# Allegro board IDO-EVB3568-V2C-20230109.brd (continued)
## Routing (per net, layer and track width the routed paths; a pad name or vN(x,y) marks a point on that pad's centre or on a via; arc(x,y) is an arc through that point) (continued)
FE1_1_DP0: length 2.8
  TOP w0.114: U8.31 106.76,44.7 106.87,44.81 106.87,45.11 106.68,45.3 106.54,45.3 106.18,45.66 106.18,45.92 R69.1
FE1_1_DP1: length 33.9
  TOP w0.114: R56.1 125.95,19.05 L8.1 125.95,19.49 125.67,19.77 125.67,19.88 v1(125.91,20.12) 125.91,20.61 R308.1 ; U8.24 112.29,42.45 112.42,42.32 115.78,42.32 117.98,40.12 117.98,31.65 118.82,30.81 118.82,29.84 v1(119.12,29.54)
  BOTTOM w0.114: v1(125.91,20.12) 125.67,20.35 125.67,20.61 125.67,20.62 125.67,22.06 124.16,23.57 123.01,23.57 118.82,27.76 118.82,29.24 v1(119.12,29.54)
FE1_1_DP2: length 45.7
  TOP w0.114: v1(114.08,11.76) 113.86,11.54 113.86,11.13 114.14,10.85 L9.1 114.14,10.41 R67.1 ; U8.21 112.11,40.95 112.26,40.81 112.69,40.81 113.11,41.22 115.01,41.22 117.25,38.99 117.25,29.62 116.41,28.78 114.38,28.78 113.51,27.91 113.51,25.26 113.1,24.85 112.77,24.85 v1(112.47,24.56)
  BOTTOM w0.114: v1(112.47,24.56) 112.19,24.84 110.02,24.84 109.3,24.12 109.3,14.94 111.65,12.58 113.56,12.58 113.86,12.27 113.86,11.99 v1(114.08,11.76)
FE1_1_DP3: length 41.5
  TOP w0.114: v1(103.44,11.76) 103.48,11.72 103.48,10.85 103.65,10.68 L10.1 103.85,10.39 R78.1 ; v1(111.65,25.81) 111.95,26.11 112.19,26.11 112.52,26.44 112.52,27.98 114.1,29.55 116,29.55 116.4,29.95 116.4,35.04 115.67,35.76 115.67,37.6 114.6,38.67 113.38,38.67 112.92,39.13 112.88,39.13 112.71,39.31 112.24,39.31 112.1,39.45 U8.18
  BOTTOM w0.114: v1(103.44,11.76) 103.19,12.01 103.19,12.52 107.76,17.08 107.76,24.19 109.67,26.11 111.35,26.11 v1(111.65,25.81)
FE1_1_DP4: length 22.8
  TOP w0.114: U8.15 110.52,37.95 110.39,37.82 108.6,37.82 106.91,39.51 106.91,42.41 v1(107.15,42.65) ; R341.2 101.97,49.67 101.97,49.43 102.45,48.96 103.96,48.96 104.1,48.82 104.1,48.69 v1(103.79,48.38)
  BOTTOM w0.114: v1(103.79,48.38) 104.09,48.68 104.09,48.87 104.37,49.15 106.92,49.15 107.51,48.56 107.51,47.09 106.87,46.46 106.87,42.94 v1(107.15,42.65)
FE1_1_XIN: length 7.1
  TOP w0.203: XT1.1 111.84,32.28 R68.1 111.51,32.21 111.07,32.21 110.64,32.65 C49.2 110.29,32.37 110.01,32.37 109.76,32.62 U8.12
FE1_1_XOUT: length 9.9
  TOP w0.203: U8.11 109.26,32.5 109.96,31.8 110.28,31.8 C51.2 110.76,31.51 110.95,31.7 111.26,31.7 R68.2 111.64,31.38 112.34,32.08 113.95,32.08 XT1.3
GMAC0_MCLKINOUT: length 55.7
  TOP w0.127: J2.230 26.92,54.23 27.38,54.69 v1(27.38,54.81) ; C131.2 v1(44.08,39.27) R219.2 R216.1
  BOTTOM w0.127: v1(44.08,39.27) 43.9,39.45 41.27,39.45 40.87,39.04 40.59,39.04 39.62,38.07 39.62,35.43 37.8,33.6 37.29,33.6 35.89,32.21 35.89,31.45 34.15,29.71 33.68,29.71 32.88,28.91 27.18,28.91 24.75,31.33 24.75,31.33 24.43,31.65 24.43,43.13 25.5,44.2 25.5,44.51 25.5,50.19 27.25,51.94 27.25,54.69 v1(27.38,54.81)
GMAC0_MDC: length 19.3
  TOP w0.127: U19.13 32,41.21 31.91,41.3 31.75,41.3 31.42,41.63 28.8,41.63 28.65,41.48 28.65,41.15 28.52,41.02 26.95,41.02 26.07,41.9 26.07,42.18 25.73,42.52 25.73,44.88 26.64,45.79 26.64,52.25 26.42,52.47 J2.232
GMAC0_MDIO: length 19.7
  TOP w0.127: U19.14 31.99,40.81 31.83,40.97 31.7,40.97 31.29,41.38 29.7,41.38 R249.1 29.06,40.74 26.82,40.74 25.78,41.78 25.78,42.06 25.45,42.39 25.45,44.96 26.39,45.9 26.39,51.99 25.92,52.46 J2.234
GMAC0_RSTN_GPIO2_D5: length 65.7
  TOP w0.127: J2.77 67.17,59.81 66.98,59.61 66.95,59.61 v1(66.9,59.56) ; R248.1 27,41.63 25.98,42.65 25.98,44.75 27.15,45.92 29.24,45.92 30.26,46.95 30.26,47.66 31.45,48.84 33.22,48.84 33.71,48.36 35.05,48.36 36.73,46.69 38.43,46.69 39.83,45.29 41.22,45.29 41.45,45.52 42.06,45.52 v1(42.19,45.39)
  BOTTOM w0.127: v1(66.9,59.56) 67.13,59.33 67.13,47.19 64.85,44.91 55.47,44.91 53.39,46.99 52.22,46.99 50.39,45.16 42.72,45.16 42.69,45.19 42.39,45.19 v1(42.19,45.39)
GMAC0_RXCLK: length 44
  TOP w0.127: C147.2 34.37,31.19 v1(34.11,31.45) R256.2 ; v1(28.52,55.83) 28.4,55.96 28.4,60.4 28.67,60.68 J2.223
  BOTTOM w0.127: v1(28.52,55.83) 28.27,55.58 28.27,53.9 28.08,53.71 28.08,51.98 26.29,50.19 26.29,45.49 27,44.78 27,41.61 25.3,39.9 25.3,31.55 27.3,29.54 32.33,29.54 34.11,31.32 v1(34.11,31.45)
GMAC0_RXD0: length 33.6
  TOP w0.127: v1(29.79,54.56) 29.41,54.56 28.92,54.07 J2.222 ; R252.2 v1(32.08,31.57)
  BOTTOM w0.127: v1(32.08,31.57) 31.32,30.81 27.58,30.81 26.37,32.03 26.37,38.76 28.02,40.41 28.02,45.42 27.41,46.02 27.41,49.66 29.13,51.38 29.13,53.14 29.79,53.8 v1(29.79,54.56)
GMAC0_RXD1: length 38.5
  TOP w0.127: R253.2 v1(31.06,31.57) ; J2.224 28.42,54.08 29.6,55.26 v1(29.81,55.26)
  BOTTOM w0.127: v1(31.06,31.57) 31.57,32.08 32.33,32.08 32.59,31.83 32.59,31.32 31.83,30.56 27.46,30.56 26.11,31.9 26.11,38.89 27.76,40.54 27.76,45.29 27.15,45.9 27.15,49.78 28.88,51.51 28.88,53.26 29.3,53.68 29.3,54.75 v1(29.81,55.26)
GMAC0_RXD2: length 36.9
  TOP w0.127: J2.219 29.67,57.6 30.94,56.34 v1(30.94,55.6) ; R254.2 v1(30.05,31.57)
  BOTTOM w0.127: v1(30.05,31.57) 29.54,31.06 27.71,31.06 26.62,32.16 26.62,38.63 28.27,40.28 28.27,45.54 27.66,46.15 27.66,49.53 29.39,51.26 29.39,53.01 30.43,54.05 30.43,55.07 30.94,55.58 v1(30.94,55.6)
GMAC0_RXD3: length 35.5
  TOP w0.127: v1(30.94,54.91) 30.43,55.42 30.43,56.34 29.41,57.35 29.41,60.4 29.17,60.64 J2.221 ; R255.2 v1(29.03,31.57)
  BOTTOM w0.127: v1(30.94,54.91) 30.94,54.18 29.64,52.88 29.64,51.13 27.91,49.4 27.91,46.28 28.57,45.62 28.57,40.21 26.87,38.51 26.87,32.28 27.84,31.32 28.78,31.32 v1(29.03,31.57)
GMAC0_RXDV_CRS: length 39.5
  TOP w0.127: R257.2 v1(33.1,31.57) ; J2.226 27.92,54.09 28.65,54.81 28.65,55.19 29.41,55.96 v1(29.92,55.96)
  BOTTOM w0.127: v1(33.1,31.57) 33.1,31.32 32.08,30.3 27.33,30.3 25.86,31.78 25.86,39.01 27.51,40.67 27.51,45.16 26.9,45.77 26.9,49.91 28.63,51.64 28.63,53.39 29.03,53.8 29.03,55.14 29.84,55.96 v1(29.92,55.96)
GMAC0_TXCLK: length 3
  TOP w0.127: J2.229 27.17,62.9 27.1,62.97 C134.2 R234.1
GMAC0_TXCLK_: length 42.4
  TOP w0.127: v1(25.35,65.23) C135.2 25.37,64.53 26.21,64.53 R234.2 ; v1(30.53,38.05) 31.83,38.05 32.19,38.41 U19.20
  BOTTOM w0.127: v1(30.53,38.05) 29.67,38.91 29.67,45.29 28.42,46.53 28.42,49.15 30.15,50.88 30.15,52.63 34.26,56.74 34.26,57.84 34.75,58.32 34.75,62.94 33.76,63.93 27.03,63.93 25.73,65.23 v1(25.35,65.23)
GMAC0_TXD0: length 2.6
  TOP w0.127: J2.216 30.42,51.21 R224.1
GMAC0_TXD0_: length 13.5
  TOP w0.127: v1(31.19,39.21) U19.18 ; R224.2 30.81,48.59 29.67,47.45 v1(29.67,47.24)
  BOTTOM w0.127: v1(29.67,47.24) 29.67,46.81 31.45,45.03 31.45,41.48 30.82,40.86 30.82,40.42 31.19,40.06 v1(31.19,39.21)
GMAC0_TXD1: length 2.5
  TOP w0.127: R227.1 29.92,50.95 J2.218
GMAC0_TXD1_: length 13.5
  TOP w0.127: v1(30.68,39.83) 30.81,39.95 31.14,39.95 31.49,39.61 U19.17 ; R227.2 29.9,49.82 v1(29.9,48.72)
  BOTTOM w0.127: v1(29.9,48.72) 29.9,48.16 29.18,47.45 29.18,46.91 31.19,44.91 31.19,41.61 30.56,40.97 30.56,39.95 v1(30.68,39.83)
GMAC0_TXD2: length 2.5
  TOP w0.127: J2.225 28.17,62.85 R228.1
GMAC0_TXD2_: length 36
  TOP w0.127: U19.16 31.8,40.01 31.72,40.08 v1(31.67,40.08) ; v1(28.19,65.2) 28.89,64.51 R228.2
  BOTTOM w0.127: v1(28.19,65.2) 28.7,64.69 34.19,64.69 35.51,63.37 35.51,57.91 35.03,57.43 35.03,56.36 30.94,52.27 30.94,48.66 30.43,48.15 30.43,46.81 31.95,45.29 31.95,40.36 v1(31.67,40.08)
GMAC0_TXD3: length 2.3
  TOP w0.127: R231.1 27.67,63.27 J2.227
GMAC0_TXD3_: length 36.2
  TOP w0.127: R231.2 27.69,64.84 27.69,64.97 v1(27.46,65.2) ; v1(31.32,40.67) 31.37,40.72 31.7,40.72 32.01,40.41 U19.15
  BOTTOM w0.127: v1(27.46,65.2) 28.22,64.44 34.01,64.44 35.26,63.19 35.26,58.06 34.77,57.58 34.77,56.47 30.68,52.38 30.68,48.77 30.18,48.26 30.18,46.69 31.7,45.16 31.7,41.05 v1(31.32,40.67)
GMAC0_TXEN: length 2.7
  TOP w0.127: J2.220 29.42,51.46 R232.1
GMAC0_TXEN_: length 14.4
  TOP w0.127: U19.19 31.82,38.81 v1(31.67,38.66) ; v1(29.24,48.16) 29.41,48.34 29.41,49.23 28.78,49.86 R232.2
  BOTTOM w0.127: v1(29.24,48.16) 28.93,47.85 28.93,46.79 30.56,45.16 30.56,43.64 30.18,43.26 30.18,39.45 30.96,38.66 v1(31.67,38.66)
GMAC1_MCLKINOUT_M1: length 22.7
  TOP w0.127: J2.54 72.92,54.05 72.42,54.56 v1(71.6,54.56) ; R271.2 v1(67.19,38.3) C155.2 R270.1
  BOTTOM w0.127: v1(71.6,54.56) 71.6,54.2 70.43,53.04 70.43,43.2 67.64,40.41 67.64,38.75 v1(67.19,38.3)
GMAC1_MDC_M1: length 39.7
  TOP w0.127: v1(56.46,41.45) 56.74,41.45 57.12,41.08 U20.13 ; J2.48 74.42,54.25 74.12,54.56 v1(73.1,54.56)
  BOTTOM w0.127: v1(73.1,54.56) 73.1,53.54 70.94,51.38 70.94,42.88 68.15,40.08 68.15,38.18 67.51,37.54 62.18,37.54 61.29,36.65 57.1,36.65 55.58,38.18 55.58,40.56 v1(56.46,41.45)
GMAC1_MDIO_M1: length 54.2
  TOP w0.127: U20.14 57.13,40.68 56.97,40.84 56.34,40.84 56.08,40.59 56.08,39.83 R297.1 55.57,38.93 54.81,38.18 54.33,38.18 53.92,37.77 53.92,37.03 v1(53.67,36.78) ; v1(75.87,51.16) 75.23,51.16 73.92,52.47 J2.50
  BOTTOM w0.127: v1(53.67,36.78) 54.13,36.32 54.13,35.53 53.04,34.44 53.04,32.72 53.8,31.95 56.21,31.95 57.73,30.43 64.47,30.43 65.43,31.39 67.1,31.39 67.47,31.76 67.47,31.93 68.55,33.02 68.55,34.7 69.44,35.59 70.38,35.59 71.58,36.78 71.58,37.69 73.74,39.85 73.74,48.97 75.87,51.1 v1(75.87,51.16)
GMAC1_RSTN_GPIO2_D7: length 34
  TOP w0.127: R296.1 54.67,41.29 v1(55.09,40.87) ; v1(68.38,60.15) 68.3,60.15 68.17,60.27 J2.73
  BOTTOM w0.127: v1(55.09,40.87) 56.21,41.99 61.42,41.99 62.74,40.67 64.97,40.67 65.28,40.97 65.28,41.55 66.62,42.9 66.62,44.12 68.15,45.64 68.15,59.13 68.27,59.26 68.27,60.05 v1(68.38,60.15)
GMAC1_RXCLK_M1: length 40.4
  TOP w0.127: v1(75.63,60.08) 75.17,60.54 J2.45 ; C171.2 59.11,33.3 v1(58.88,33.53) R304.2
  BOTTOM w0.127: v1(58.88,33.53) 59.46,34.11 60.91,34.11 62.05,35.26 62.05,35.89 62.69,36.53 68.02,36.53 69.67,38.18 69.67,38.48 71.96,40.77 71.96,50.11 73.36,51.51 73.36,52.27 74.37,53.29 74.37,58.83 v1(75.63,60.08)
GMAC1_RXD0_M1: length 42.3
  TOP w0.127: R300.2 v1(56.85,33.6) ; J2.34 77.92,54.56 v1(77.93,54.56)
  BOTTOM w0.127: v1(56.85,33.6) 56.85,32.97 58.14,31.67 62.15,31.67 63.2,32.72 67.51,32.72 68.05,33.25 68.05,35.02 69.12,36.09 70.13,36.09 70.94,36.91 70.94,37.82 73.23,40.11 73.23,49.23 75.13,51.13 75.13,52.15 76.28,53.29 76.28,54.58 76.76,55.07 77.42,55.07 v1(77.93,54.56)
GMAC1_RXD1_M1: length 41.8
  TOP w0.127: v1(77.17,54.56) 77.42,54.3 J2.36 ; R301.2 v1(55.83,33.6)
  BOTTOM w0.127: v1(77.17,54.56) 76.53,53.92 76.53,53.04 75.39,51.89 75.39,51 73.48,49.1 73.48,39.98 71.2,37.69 71.2,36.76 70.28,35.84 69.27,35.84 68.3,34.87 68.3,33.12 67.64,32.46 63.3,32.46 62.23,31.39 58.04,31.39 v1(55.83,33.6)
GMAC1_RXD2_M1: length 45.8
  TOP w0.127: v1(76.35,62.69) 76.3,62.69 76.17,62.56 J2.41 ; v1(54.84,33.6) 54.84,34.14 R302.2
  BOTTOM w0.127: v1(76.35,62.69) 76.35,61.85 73.86,59.36 73.86,53.54 71.45,51.13 71.45,42.62 68.66,39.83 68.66,37.92 67.77,37.03 62.43,37.03 61.54,36.14 61.54,35.51 60.88,34.85 56.08,34.85 v1(54.84,33.6)
GMAC1_RXD3_M1: length 45.8
  TOP w0.127: R303.2 53.8,33.88 54.08,33.6 v1(54.15,33.6) ; J2.43 v1(75.67,62.53)
  BOTTOM w0.127: v1(75.67,62.53) 75.67,61.55 73.61,59.49 73.61,53.67 71.2,51.26 71.2,42.75 68.4,39.95 68.4,38.05 67.64,37.29 62.31,37.29 61.29,36.27 61.29,35.64 60.76,35.1 55.65,35.1 v1(54.15,33.6)
GMAC1_RXDV_CRS_M1: length 37.7
  TOP w0.127: v1(75.39,54.56) 76.4,54.56 76.92,54.04 J2.38 ; R305.2 58.18,32.01 v1(58.43,32.26)
  BOTTOM w0.127: v1(58.43,32.26) 59.01,32.84 62.56,32.84 62.94,33.22 67.26,33.22 67.51,33.48 67.51,35.23 68.88,36.6 69.88,36.6 70.43,37.16 70.43,38.07 72.72,40.36 72.72,49.48 74.63,51.38 74.63,52.4 75.39,53.16 v1(75.39,54.56)
GMAC1_TXCLK_M1: length 3.6
  TOP w0.127: R282.1 C158.2 76.53,63.5 77.01,63.02 77.01,62.61 76.67,62.27 J2.39
GMAC1_TXCLK_M1_: length 44.9
  TOP w0.127: R282.2 77.47,64.73 C159.2 73.99,65.61 72.54,64.16 72.54,63.3 v1(72.31,63.07) ; v1(56.85,37.8) 57.33,38.28 U20.20
  BOTTOM w0.127: v1(56.85,37.8) 57.1,38.05 65.66,38.05 67.13,39.52 67.13,40.72 69.93,43.51 69.93,53.67 70.43,54.18 70.43,57.61 71.55,58.72 71.55,61.26 71.96,61.67 71.96,62.71 v1(72.31,63.07)
GMAC1_TXD0_M1: length 2.9
  TOP w0.127: J2.47 74.67,62.23 74.88,62.43 74.88,63.45 75.19,63.76 R272.1
GMAC1_TXD0_M1_: length 42.2
  TOP w0.127: v1(56.91,38.91) 57.07,39.08 U20.18 ; R272.2 75.39,64.66 v1(75,64.27)
  BOTTOM w0.127: v1(75,64.27) 74.43,64.27 73.91,63.75 73.51,63.75 73.05,64.21 71.83,64.21 71.45,63.83 71.45,61.93 71.03,61.5 71.03,58.98 69.16,57.11 69.16,45.15 67.67,43.65 67.67,42.39 66.34,41.07 66.34,39.9 65.33,38.89 64.54,38.89 63.88,39.55 63.3,39.55 63.07,39.32 57.86,39.32 57.45,38.91 v1(56.91,38.91)
GMAC1_TXD1_M1: length 2.6
  TOP w0.127: J2.49 74.17,62.24 74.63,62.69 74.63,63.46 R275.1
GMAC1_TXD1_M1_: length 41.3
  TOP w0.127: v1(56.49,39.46) 56.54,39.41 57.28,39.41 57.35,39.48 U20.17 ; v1(73.69,64.24) 74.11,64.66 R275.2
  BOTTOM w0.127: v1(73.69,64.24) 73.43,64.49 71.73,64.49 71.2,63.96 71.2,62.05 70.76,61.62 70.76,59.08 68.91,57.23 68.91,45.26 67.41,43.76 67.41,42.52 66.04,41.15 66.04,40.06 65.15,39.17 64.64,39.17 63.98,39.83 63.2,39.83 62.94,39.57 57.73,39.57 57.56,39.4 56.55,39.4 v1(56.49,39.46)
GMAC1_TXD2_M1: length 3.7
  TOP w0.127: J2.35 77.67,62.28 78.33,62.94 79.14,62.94 R276.1
GMAC1_TXD2_M1_: length 45.4
  TOP w0.127: v1(57.05,39.88) U20.16 ; R276.2 79.43,64.66 v1(79.38,64.72)
  BOTTOM w0.127: v1(57.05,39.88) 59.06,39.88 59.77,40.59 60.43,40.59 60.88,40.13 65.28,40.13 65.79,40.64 65.79,41.3 67.13,42.65 67.13,43.87 68.66,45.39 68.66,57.4 70.49,59.23 70.49,61.73 70.94,62.18 70.94,64.08 71.6,64.74 77.27,64.74 77.77,64.24 78.36,64.24 78.84,64.72 v1(79.38,64.72)
GMAC1_TXD3_M1: length 3
  TOP w0.127: R279.1 78.65,63.76 77.17,62.29 J2.37
GMAC1_TXD3_M1_: length 44.7
  TOP w0.127: v1(56.57,40.36) 57.25,40.36 57.33,40.28 U20.15 ; v1(78.16,64.72) 78.21,64.66 R279.2
  BOTTOM w0.127: v1(78.16,64.72) 77.88,65 71.48,65 70.69,64.21 70.69,62.31 70.23,61.85 70.23,59.36 68.4,57.53 68.4,45.52 66.88,43.99 66.88,42.77 65.53,41.43 65.53,40.77 65.18,40.41 61.01,40.41 60.58,40.84 59.64,40.84 59.16,40.36 v1(56.57,40.36)
GMAC1_TXEN_M1: length 3.2
  TOP w0.127: R280.1 78.42,50.83 J2.32
GMAC1_TXEN_M1_: length 52.7
  TOP w0.127: U20.19 57.35,38.68 57.1,38.43 56.72,38.43 56.34,38.81 55.83,38.81 54.94,37.92 54.46,37.92 54.18,37.64 54.18,36.58 v1(53.64,36.04) ; v1(78.33,49.73) 78.66,49.41 R280.2
  BOTTOM w0.127: v1(53.64,36.04) 53.64,35.46 52.78,34.59 52.78,31.7 53.54,30.94 56.85,30.94 57.61,30.18 66.24,30.18 67.72,31.66 67.72,31.83 68.81,32.91 68.81,34.59 69.55,35.33 70.51,35.33 71.83,36.65 71.83,37.54 73.99,39.7 73.99,48.82 74.78,49.61 78.21,49.61 v1(78.33,49.73)
HDMI_TX_CEC_PORT: length 7.7
  TOP w0.127: Q5.3 68.17,75.87 67.82,76.23 66.09,76.23 65.74,76.58 65.74,77.5 65.23,78 D44.1 65.23,78.82 64.75,79.29 J14.13
HDMI_TX_CLKN: length 25.5
  TOP w0.102: L19.2 64.15,74.44 63.89,74.17 63.89,74.06 v1(64.11,73.84) ; J2.147 47.67,62.23 47.55,62.36 47.55,63.04 v1(47.77,63.26)
  L3-POW w0.097: v1(47.77,63.26) 47.58,63.45 47.58,64.05 47.8,64.27 49.45,64.27 55.95,70.77 59.18,70.77 59.39,70.56 59.39,70.28 59.66,70.01 60.26,70.01 60.53,70.28 60.53,70.56 61.63,71.66 62.31,71.66 63.92,73.27 63.92,73.65 v1(64.11,73.84)
HDMI_TX_CLKN_: length 4.9
  TOP w0.102: L19.3 64.15,76.33 63.87,76.62 63.87,76.85 63.99,76.97 D41.5 D41.6 63.99,78.6 63.88,78.72 63.88,79.12 64.25,79.49 J14.12
HDMI_TX_CLKP: length 25.5
  TOP w0.102: v1(63.42,73.84) 63.64,74.06 63.64,74.16 63.35,74.44 L19.1 ; J2.149 47.17,62.24 47.3,62.36 47.3,63.04 v1(47.08,63.26)
  L3-POW w0.097: v1(63.42,73.84) 63.62,73.63 63.62,73.39 62.19,71.96 61.5,71.96 60.23,70.69 60.23,70.4 60.13,70.31 59.78,70.31 59.68,70.4 59.68,70.69 59.3,71.07 55.83,71.07 49.33,64.57 47.68,64.57 47.28,64.17 47.28,63.47 v1(47.08,63.26)
HDMI_TX_CLKP_: length 4.9
  TOP w0.102: J14.10 63.25,79.49 63.62,79.12 63.62,78.74 63.49,78.6 D41.7 D41.4 63.49,77 63.61,76.87 63.61,76.62 63.35,76.36 L19.4
HDMI_TX_D0N: length 25.6
  TOP w0.102: J2.155 45.67,62.21 45.8,62.33 45.8,62.56 46.09,62.86 46.09,63.89 45.99,63.99 45.89,63.99 v1(45.67,63.78) ; v1(62.59,73.81) 62.36,74.04 62.36,74.15 62.64,74.43 L18.2
  L3-POW w0.097: v1(45.67,63.78) 45.88,63.98 46.24,63.98 47.32,65.05 49.1,65.05 55.6,71.56 60.42,71.56 61.33,72.47 61.93,72.47 62.45,72.99 62.45,73.67 v1(62.59,73.81)
HDMI_TX_D0N_: length 4.9
  TOP w0.102: L18.3 62.64,76.35 62.37,76.62 62.37,76.85 62.49,76.97 D41.2 D41.9 62.49,78.62 62.37,78.75 62.37,79.11 62.75,79.49 J14.9
HDMI_TX_D0P: length 25.5
  TOP w0.102: L18.1 61.84,74.43 62.11,74.16 62.11,74.02 v1(61.9,73.81) ; J2.153 46.17,62.21 46.05,62.33 46.05,62.45 46.35,62.75 46.35,64 46.1,64.25 45.89,64.25 v1(45.67,64.47)
  L3-POW w0.097: v1(45.67,64.47) 45.86,64.28 46.12,64.28 47.19,65.35 48.97,65.35 55.47,71.86 60.3,71.86 61.21,72.77 61.8,72.77 62.15,73.12 62.15,73.56 v1(61.9,73.81)
HDMI_TX_D0P_: length 4.8
  TOP w0.102: J14.7 61.75,79.5 62.12,79.13 62.12,78.75 61.99,78.62 D41.10 D41.1 61.99,76.97 62.12,76.85 62.12,76.62 61.84,76.35 L18.4
HDMI_TX_D1N: length 25.7
  TOP w0.102: J2.159 44.67,62.2 44.8,62.32 44.8,62.6 44.91,62.71 44.91,63.72 44.8,63.83 44.63,63.83 v1(44.4,63.6) ; L17.2 61.14,74.43 60.87,74.15 60.87,74.03 v1(61.09,73.82)
  L3-POW w0.097: v1(61.09,73.82) 60.91,73.64 60.91,73.15 60.1,72.34 55.24,72.34 48.74,65.84 46.03,65.84 45.19,65 45.19,64.1 44.92,63.82 44.62,63.82 v1(44.4,63.6)
HDMI_TX_D1N_: length 4.9
  TOP w0.102: J14.6 61.25,79.49 60.88,79.12 60.88,78.55 60.99,78.44 D40.6 D40.5 60.99,76.97 60.87,76.85 60.87,76.62 61.14,76.35 L17.3
HDMI_TX_D1P: length 25.6
  TOP w0.102: J2.157 45.17,62.19 45.05,62.32 45.05,62.5 45.16,62.61 45.16,63.83 44.91,64.08 44.61,64.08 v1(44.4,64.29) ; L17.1 60.34,74.43 60.62,74.16 60.62,74.04 v1(60.39,73.82)
  L3-POW w0.097: v1(60.39,73.82) 60.61,73.6 60.61,73.28 59.98,72.64 55.12,72.64 48.62,66.14 45.91,66.14 44.89,65.12 44.89,64.22 44.79,64.12 44.57,64.12 v1(44.4,64.29)
HDMI_TX_D1P_: length 4.9
  TOP w0.102: L17.4 60.34,76.35 60.62,76.62 60.62,76.85 60.49,76.97 D40.4 D40.7 60.49,78.42 60.62,78.55 60.62,79.13 60.25,79.5 J14.4
HDMI_TX_D2N: length 25.6
  TOP w0.102: v1(43.13,63.6) 43.35,63.82 43.54,63.82 43.66,63.7 43.66,62.63 43.8,62.5 43.8,62.34 43.67,62.22 J2.163 ; v1(59.6,73.84) 59.37,74.07 59.37,74.13 59.65,74.4 L16.2
  L3-POW w0.097: v1(43.13,63.6) 43.34,63.8 43.61,63.8 43.94,64.13 43.94,65.53 45.03,66.62 48.38,66.62 54.89,73.13 59.12,73.13 59.4,73.4 59.4,73.64 v1(59.6,73.84)
HDMI_TX_D2N_: length 4.9
  TOP w0.102: L16.3 59.65,76.37 59.37,76.65 59.37,76.87 59.49,77 D40.2 D40.9 59.49,78.4 59.38,78.52 59.38,78.99 59.75,79.36 J14.3
HDMI_TX_D2P: length 25.5
  TOP w0.102: L16.1 58.85,74.4 59.12,74.13 59.12,74.06 v1(58.9,73.84) ; v1(43.13,64.29) 43.35,64.07 43.65,64.07 43.92,63.8 43.92,62.74 44.05,62.6 44.05,62.33 44.17,62.2 J2.161
  L3-POW w0.097: v1(43.13,64.29) 43.32,64.1 43.49,64.1 43.64,64.25 43.64,65.65 44.91,66.92 48.25,66.92 54.76,73.43 59,73.43 59.1,73.53 59.1,73.65 v1(58.9,73.84)
HDMI_TX_D2P_: length 4.9
  TOP w0.102: L16.4 58.85,76.37 59.12,76.64 59.12,76.87 58.99,77 D40.1 D40.10 58.99,78.4 59.12,78.53 59.12,78.98 58.75,79.35 J14.1
HDMI_TX_HPD_PORT: length 6.2
  TOP w0.127: R107.2 69.93,77.05 R108.2 69.37,77.07 69.32,77.02 D46.1 68.48,77.37 68.48,77.42 68.2,77.7 68.2,78.28 67.75,78.73 J14.19
HDMI_TX_HPDIN: length 36.5
  TOP w0.127: R107.1 71.08,78.13 v1(71.45,78.13) ; J2.143 50.67,65.19 54.05,68.57 54.05,74.02 53.78,74.29 v1(53.78,74.3)
  BOTTOM w0.127: v1(71.45,78.13) 71.15,78.44 69.42,78.44 68.4,79.45 57.79,79.45 57.44,79.11 56.85,78.51 55.95,78.51 53.95,76.52 53.95,74.84 53.78,74.68 v1(53.78,74.3)
HDMI_TXDDC_SCL_PORT: length 12.3
  TOP w0.127: J14.15 65.75,78.75 D45.1 65.99,77.49 65.99,76.68 66.19,76.48 68.01,76.48 68.73,75.77 69.74,75.77 Q3.3 70.03,75.33 69.16,74.46 69.16,72.83 R104.1
HDMI_TXDDC_SDA_PORT: length 12.6
  TOP w0.127: J14.16 66.25,79.37 D47.1 67.61,77.93 68.22,77.32 68.22,76.63 68.75,76.1 71.45,76.1 71.89,75.66 71.89,75.48 Q4.3 71.69,75.48 70.89,74.68 70.89,73 71.17,72.72 R106.2
HDMITX_CEC_M0: length 28.1
  TOP w0.127: v2(74.98,71.03) 74.98,70.82 75.03,70.76 75.03,68.53 74.88,68.38 70.94,64.44 67.68,64.44 66.99,63.75 65.61,63.75 64.17,62.32 J2.89 ; Q5.2 68.55,73.88 68,73.33 R109.1 68.53,72.18 68.53,70.51 v1(68.55,70.48)
  BOTTOM w0.127: v2(74.98,71.03) 74.82,71.03 74.69,71.16 74.46,71.16 74.19,71.42 72.39,71.42 71.6,70.64 71.04,70.64 70.66,71.02 69.75,71.02 69.19,70.46 68.63,70.46 68.61,70.48 v1(68.55,70.48)
HOST_WAKE_BT: length 2.7
  TOP w0.127: U18.6 112.85,18.62 113.87,17.6 R394.2
HOST_WAKE_BT_H_GPIO1_D3: length 74.2
  TOP w0.127: v1(94.03,27) 93.6,27 93.47,26.87 93.47,26.03 91.72,24.28 89.28,24.28 87.53,26.04 82.7,26.04 82.37,26.37 82.37,35.76 82.25,35.89 82.25,40.72 81.42,41.54 J2.20 ; v1(116.15,17.6) R394.1
  BOTTOM w0.127: v1(94.03,27) 93.78,27.25 93.78,28.24 94.51,28.98 108.84,28.98 109.34,28.48 111.24,28.48 114.5,25.22 114.5,19.25 v1(116.15,17.6)
HP_SNS: length 231.3
  TOP w0.203: v1(122.61,74.07) 122.25,74.42 122.25,75.51 121.93,75.84 R81.1 120.22,77.23 120.22,81.74 121.67,83.19 121.67,85.88 121.11,86.44 115.65,86.44 J10.1 ; v1(36.78,27.25) 36.78,27.51 35.64,28.65 28.52,28.65 27.13,30.05 27.13,31.45 26.75,31.83 26.41,31.83 25.35,31.83 23.55,33.63 19.52,33.63 18.13,35.02 18.13,37.11 16.69,38.56 16.69,49.52 16.88,49.72 17.28,50.11 17.82,50.11 21.87,50.11 23.42,51.67 J2.244
  BOTTOM w0.203: v1(122.61,74.07) 123.19,74.07 125.27,71.98 125.27,68.76 124.79,68.28 124.79,64.95 125.27,64.47 125.27,61.7 127.73,59.24 127.73,48.99 126.97,48.23 126.97,40.61 125.93,39.57 114.55,39.57 112.52,37.54 112.09,37.54 109.55,35 101.17,35 100.57,34.4 96.92,34.4 94.65,32.13 89.28,32.13 88.47,31.32 87.58,31.32 86.46,30.2 86.46,29.31 84.99,27.84 84.99,26.95 75.39,17.35 75.39,13.16 69.75,7.52 39.47,7.52 38.3,8.69 37.85,8.69 36.65,9.88 36.65,12.88 36.98,13.21 36.98,26.29 36.78,26.49 v1(36.78,27.25)
HPL_OUT: length 217.1
  TOP w0.203: C72.2 115.11,74.94 R84.1 v1(115.77,74.22) ; J2.242 23.92,51.61 22.1,49.78 17.69,49.78 17.41,49.78 17.02,49.39 17.02,42.96 17.02,42.96 17.02,38.84 18.61,37.25 18.61,35.01 19.63,33.99 23.67,33.99 25.49,32.17 26.99,32.17 27.46,31.7 27.46,30.2 28.63,29.03 35.76,29.03 37.29,27.51 v1(37.29,26.75)
  BOTTOM w0.203: v1(37.29,26.75) 37.34,26.7 37.34,13.08 36.98,12.73 36.98,10.06 38.02,9.02 38.46,9.02 39.6,7.87 69.6,7.87 75.01,13.28 75.01,17.48 84.66,27.13 84.66,28.02 86.13,29.49 86.13,30.38 87.4,31.65 88.29,31.65 89.1,32.46 94.51,32.46 96.8,34.75 100.43,34.75 101.04,35.36 109.4,35.36 111.96,37.92 112.42,37.92 114.45,39.95 125.81,39.95 126.64,40.79 126.64,48.42 127.37,49.15 127.37,59.09 124.94,61.52 124.94,64.21 124.41,64.74 124.41,68.38 124.94,68.91 124.94,71.76 123.53,73.18 119.51,73.18 118.95,73.74 116.26,73.74 v1(115.77,74.22)
HPR_OUT: length 216.3
  TOP w0.203: C75.2 R82.1 v1(119.58,74.37) ; v1(36.27,26.77) 36.27,27.38 35.38,28.27 28.42,28.27 26.8,29.9 26.8,31.24 26.54,31.5 25.19,31.5 23.42,33.27 19.41,33.27 17.64,35.04 17.64,37.09 16.31,38.43 16.31,49.61 16.36,49.66 17.14,50.44 17.96,50.44 21.64,50.44 22.92,51.73 J2.246
  BOTTOM w0.203: v1(36.27,26.77) 36.27,26.52 36.63,26.16 36.63,13.34 36.32,13.03 36.32,9.73 37.72,8.33 38.18,8.33 39.32,7.19 69.93,7.19 75.77,13.03 75.77,17.22 85.32,26.77 85.32,27.66 86.79,29.13 86.79,30.02 87.71,30.94 88.6,30.94 89.46,31.8 94.84,31.8 97,33.96 100.63,33.96 101.3,34.62 109.68,34.62 112.22,37.16 112.62,37.16 114.66,39.19 126.06,39.19 127.33,40.46 127.33,48.08 128.07,48.82 128.07,59.41 125.6,61.87 125.6,64.67 125.2,65.07 125.2,68.05 125.6,68.45 125.6,72.16 123.19,74.57 122.33,74.57 121.62,73.86 120.09,73.86 v1(119.58,74.37)
HUB_RST: length 5.2
  TOP w0.254: U8.34 105.26,44.88 104.47,45.67 103.96,45.67 103.71,45.92 R53.2
  TOP w0.381: C48.2 R66.1 R53.2
HUB_RST_GPIO1_A4_D: length 25.2
  TOP w0.127: R53.1 102.69,48.16 99.72,48.16 98.07,46.51 v1(97.71,46.51) ; v1(84.02,51.54) 84.02,51.89 84.42,52.29 J2.8
  BOTTOM w0.127: v1(97.71,46.51) 97.41,46.81 95.61,46.81 94.72,47.7 89.87,47.7 85.55,52.02 84.51,52.02 v1(84.02,51.54)
I2C1_SCL: length 122.1
  TOP w0.127: v1(50.37,41.12) 50.75,41.5 50.75,42.85 50.27,43.33 50.27,46.71 47.7,49.28 47.7,52.05 47.92,52.27 J2.146 ; R311.2 127.14,29.08 125.26,30.96 125.16,30.96 124.93,31.19 124.66,31.19 124.16,31.7 120.85,31.7 119.76,32.79 119.76,35.56 120.6,36.4 120.6,41.61 v1(120.85,41.86)
  BOTTOM w0.127: v1(120.85,41.86) 120.35,41.35 117.68,41.35 117.17,41.86 113.74,41.86 109.42,37.54 106.5,37.54 105.74,36.78 100.28,36.78 99.9,36.4 97.22,36.4 94.42,39.19 78.05,39.19 67.26,28.4 56.72,28.4 55.96,29.16 52.65,29.16 51,30.81 51,39.04 50.37,39.68 50.37,40.46 50.37,40.46 v1(50.37,41.12)
I2C1_SCL_: length 6.3
  TOP w0.127: R311.7 128.91,29.08 130.51,30.68 132.28,30.68 J24.22
I2C1_SDA: length 122.5
  TOP w0.127: v1(121.36,41.35) 120.85,40.84 120.85,40.42 120.85,36.27 120.02,35.43 120.02,32.92 120.98,31.95 124.28,31.95 124.79,31.45 125.04,31.45 125.27,31.21 125.36,31.21 126.95,29.63 R311.1 ; v1(49.82,40.59) 49.82,41.28 50.5,41.96 50.5,42.72 50.01,43.21 50.01,46.58 47.45,49.15 47.45,53.23 J2.148
  BOTTOM w0.127: v1(121.36,41.35) 121.11,41.1 117.55,41.1 117.04,41.61 113.87,41.61 109.55,37.29 106.63,37.29 105.87,36.53 100.41,36.53 100.03,36.14 97.11,36.14 94.32,38.94 78.18,38.94 67.39,28.14 52.66,28.14 50.75,30.05 50.75,38.94 50.09,39.6 50.09,40.31 49.82,40.58 v1(49.82,40.59)
I2C1_SDA_: length 3.5
  TOP w0.127: R311.8 128.49,29.63 128.84,29.98 129.04,29.98 J24.21
I2C2_SCL_M0: length 65
  TOP w0.127: J2.150 46.92,52.16 47.19,51.89 47.19,49.02 49.76,46.46 49.76,42.79 v1(50.02,42.53) ; v1(39.28,20.39) 39.31,20.42 41.63,20.42 42.75,19.3 43.36,19.3 v1(43.74,18.92)
  BOTTOM w0.127: v1(39.28,20.39) 38.62,20.39 38.25,20.76 38.25,26.23 38.51,26.49 38.51,27.66 38.11,28.06 37.9,28.06 34.37,28.06 32.9,26.59 32.48,26.59 32.31,26.59 32.21,26.49 32.21,25.79 R111.1 R115.1 ; v1(43.74,18.92) 45.31,18.92 46.08,19.68 46.08,20.19 47.22,21.34 49.28,21.34 50.5,22.56 50.5,26.62 49.48,27.64 49.48,36.78 48.84,37.41 48.84,41.71 49.56,42.42 49.85,42.42 49.96,42.53 v1(50.02,42.53)
I2C2_SDA_M0: length 64.1
  TOP w0.127: v1(42.85,18.8) 41.48,20.17 39.77,20.17 39.47,19.86 39.19,19.86 39.08,19.97 38.39,19.97 38.19,20.18 v1(38.18,20.18) ; v1(49.76,41.91) 49.5,42.16 49.5,46.33 46.94,48.9 46.94,51.77 46.42,52.28 J2.152
  BOTTOM w0.127: v1(49.76,41.91) 49.74,41.88 49.71,41.88 49.1,41.27 49.1,37.54 49.73,36.91 49.73,27.76 50.75,26.75 50.75,22.43 49.4,21.08 47.35,21.08 46.33,20.07 46.33,19.56 45.21,18.44 43.26,18.44 42.9,18.8 v1(42.85,18.8) ; R116.1 33.81,25.13 R112.1 33.83,25.2 34.32,25.68 34.32,27.58 34.54,27.8 38.01,27.8 38.26,27.55 38.26,26.59 38,26.33 38,20.36 v1(38.18,20.18)
I2C3_SCL_M1: length 57.5
  TOP w0.127: J2.74 67.92,51.76 68.28,51.41 69.14,51.41 75.9,44.65 75.9,43.26 79.71,39.45 79.71,34.62 79.83,34.49 79.83,29.16 78.05,27.38 78.05,22.94 78.56,22.43 78.56,21.53 82.07,18.02 89.78,18.02 90.25,17.55 90.25,16.38 v1(90.12,16.26) ; R96.1 92.02,15.37 R92.1 92.68,15.5 v1(92.73,15.45)
  BOTTOM w0.127: v1(92.73,15.45) 92.35,15.82 90.55,15.82 v1(90.12,16.26)
I2C3_SDA_M1: length 54.5
  TOP w0.127: R97.1 R93.1 90.59,16.04 90.59,17.56 89.88,18.27 82.18,18.27 78.82,21.63 78.82,22.56 78.31,23.06 78.31,27.25 80.09,29.03 80.09,34.62 79.96,34.75 79.96,39.57 76.15,43.38 76.15,44.78 69.27,51.66 68.88,51.66 68.42,52.13 J2.72
I2C4_SCL_M0: length 53.3
  TOP w0.127: v1(81.25,25.98) 81.25,26.52 81.86,27.13 81.86,35.51 81.74,35.64 81.74,40.46 77.93,44.27 77.93,45.67 77.6,46 77.6,50.67 77.8,50.88 77.8,51.64 77.66,51.78 76.74,51.78 76.35,52.17 76.07,52.17 75.92,52.32 J2.42 ; R152.1 63.96,15.57 v1(64.21,15.82) 64.24,15.85 R155.1
  BOTTOM w0.127: v1(64.21,15.82) 65.61,17.22 71.45,17.22 79.83,25.6 80.87,25.6 v1(81.25,25.98)
I2C4_SDA_M0: length 54.4
  TOP w0.127: R154.1 62.94,16.31 v1(62.94,15.82) R153.1 ; v1(81.86,26.47) 81.86,26.75 82.12,27 82.12,35.64 81.99,35.76 81.99,40.59 78.18,44.4 78.18,45.8 77.85,46.13 77.85,50.55 78.05,50.75 78.05,51.77 77.74,52.08 76.83,52.08 76.42,52.48 J2.40
  BOTTOM w0.127: v1(62.94,15.82) 63.35,16.23 63.98,16.23 65.23,17.48 71.32,17.48 79.71,25.86 80.47,25.86 81.08,26.47 v1(81.86,26.47)
I2C5_SCL-HDMI: length 24.2
  TOP w0.127: Q3.2 70.53,73.06 R103.2 70.66,72.23 70.66,71.06 70.98,70.75 71.66,70.75 71.83,70.92 72.97,70.92 73.2,71.15 73.8,71.15 74.52,70.43 74.52,68.97 74.45,68.91 74.45,68.66 70.73,64.95 67.46,64.95 66.78,64.26 65.13,64.26 63.17,62.31 J2.93
I2C5_SCL_M0: length 68.6
  TOP w0.127: R327.1 75.08,39.57 74.63,39.57 74.22,39.17 v1(74.22,30.05) ; R327.1 75.34,39.88 74.4,40.82 74.4,42.37 75.39,43.36 75.39,44.4 68.91,50.88 67.64,50.88 66.92,51.59 J2.78 ; R327.1 75.39,39.78 R328.2 ; v1(47.21,17.11) 47.21,17.48 46.37,18.32 44.9,18.32 Q17.3
  BOTTOM w0.127: v1(47.21,17.11) 47.24,17.14 47.24,17.5 47.62,17.88 48.54,17.88 48.64,17.98 49.63,17.98 49.96,18.31 49.96,20.13 50.26,20.43 54.17,24.33 54.38,24.33 54.59,24.33 54.59,24.33 68.37,24.33 68.37,24.33 69,24.33 69.06,24.33 74.22,29.49 v1(74.22,30.05)
I2C5_SDA-HDMI: length 21.8
  TOP w0.127: Q4.2 72.44,73.82 72.44,72.76 R105.2 74.3,72.71 74.55,72.45 74.55,70.76 74.78,70.54 74.78,68.63 70.84,64.69 67.57,64.69 66.89,64.01 65.43,64.01 63.67,62.25 J2.91
I2C5_SDA_M0: length 74
  TOP w0.127: R326.1 77.06,41.71 79.45,39.32 79.45,34.11 v1(79.32,33.99) ; R326.1 76.43,41.71 76.43,42.34 75.64,43.13 75.64,44.53 69.01,51.16 67.87,51.16 67.42,51.6 J2.76 ; R326.1 76.33,41.62 R329.2 ; Q16.3 41.87,17.35 42.62,17.35 42.81,17.53 43.19,17.53 44.28,18.63 46.42,18.63 47.64,17.41 v1(47.92,17.41)
  BOTTOM w0.127: v1(79.32,33.99) 79.3,33.96 77.77,33.96 76.53,32.72 76.53,31.39 69.22,24.08 69.11,24.08 54.48,24.08 54.48,24.08 54.27,24.08 50.22,20.02 50.22,18.21 49.74,17.73 48.79,17.73 48.31,17.25 48.08,17.25 v1(47.92,17.41)
I2C_SCL_RTC: length 2.3
  TOP w0.127: R328.1 77.93,39.78 78.07,39.63 U21.6
I2C_SDA_RTC: length 3.3
  TOP w0.127: R329.1 77.6,40.72 78.72,39.59 U21.5
LAN0_A+: length 54.8
  TOP w0.102: v1(35.36,47.4) 35.14,47.18 35.14,47.1 35.43,46.81 36.02,46.81 36.66,46.18 38.01,46.18 38.27,45.93 38.27,45.7 R223.2 ; D84.4 v1(30.39,68.15) 30.39,68 30.49,67.89 31.57,67.89 31.7,68.02 31.7,68.94 D57.A 31.95,68.94 31.95,68.02 32.08,67.89 32.23,67.89 32.33,68 32.33,72.36 28.67,76.02 27.89,76.02 27.13,75.26 27.13,74.18 27.57,73.74 28.52,73.74 28.78,73.99 28.78,74.37 28.27,74.88
  BOTTOM w0.102: v1(35.36,47.4) 35.15,47.6 35.15,51.43 38.06,54.34 38.06,56.09 38.56,56.59 38.56,65.99 36.4,68.15 32.08,68.15 31.83,67.89 30.64,67.89 v1(30.39,68.15)
LAN0_A-: length 54.6
  TOP w0.102: R222.2 38.01,45.7 38.01,45.82 37.91,45.92 36.55,45.92 35.92,46.56 35.33,46.56 34.89,47 34.89,47.16 v1(34.65,47.4) ; D84.3 v1(30.39,67.39) 30.39,67.54 30.49,67.64 31.57,67.64 31.7,67.51 31.7,66.59 D57.C 31.95,66.59 31.95,67.26 32.59,67.89 32.59,72.47 28.78,76.28 27.78,76.28 26.87,75.37 26.87,74.07 27.32,73.62 27.32,72.66 J22.3
  BOTTOM w0.102: v1(30.39,67.39) 30.64,67.64 31.93,67.64 32.19,67.89 36.29,67.89 38.3,65.88 38.3,56.69 37.81,56.2 37.81,54.44 34.9,51.54 34.9,47.64 v1(34.65,47.4)
LAN0_B+: length 54.8
  TOP w0.102: v1(33.86,47.27) 33.63,47.04 33.63,46.89 34.47,46.05 35.13,46.05 35.38,45.8 35.38,45.64 35.67,45.36 R221.2 ; v1(28.69,73.18) 28.47,72.96 28.47,71.86 29.16,71.17 29.16,70.58 28.76,70.18 28.29,70.18 27.66,70.82 26.75,70.82 26.37,70.43 26.37,68.02 26.49,67.89 26.62,67.89 26.87,68.15 26.87,68.94 D56.A 27.13,68.94 27.13,68.02 27.25,67.89 28.39,67.89 28.49,68 v1(28.49,68.15) D84.6
  BOTTOM w0.102: v1(33.86,47.27) 33.63,47.5 33.63,51.05 37.31,54.73 37.31,56.41 37.8,56.89 37.8,64.97 35.84,66.93 30,66.93 29.03,67.89 28.74,67.89 v1(28.49,68.15) ; v1(28.69,73.18) 28.47,73.4 28.47,73.63 28.2,73.91 24.42,73.91 24.21,74.12 24.21,74.63 24.46,74.88 25.73,74.88
LAN0_B-: length 54.7
  TOP w0.102: v1(33.16,47.27) 33.38,47.05 33.38,46.78 34.36,45.8 35.03,45.8 35.13,45.69 35.13,45.61 R220.2 ; v1(28,73.18) 28.22,72.96 28.22,71.75 28.91,71.07 28.91,70.69 28.65,70.43 28.4,70.43 27.76,71.07 26.64,71.07 26.11,70.54 26.11,67.92 26.39,67.64 26.62,67.64 26.87,67.39 26.87,66.59 D56.C 27.13,66.59 27.13,67.39 27.38,67.64 28.39,67.64 28.49,67.54 v1(28.49,67.39) D84.1
  BOTTOM w0.102: v1(28.49,67.39) 28.74,67.64 28.93,67.64 29.89,66.67 35.73,66.67 37.54,64.87 37.54,57 37.06,56.52 37.06,54.84 36.46,54.24 33.38,51.16 33.38,47.49 v1(33.16,47.27) ; J22.7 23.23,73.65 28.1,73.65 28.22,73.53 28.22,73.4 v1(28,73.18)
LAN0_C+: length 54.6
  TOP w0.102: v1(32.87,46.65) 32.66,46.44 32.66,46.28 32.77,46.18 33.27,46.18 33.63,45.82 33.63,45.71 R425.2 ; v1(23,68.28) D83.4 23.36,69.24 23.57,69.04 23.57,68.15 23.7,68.02 24.08,68.02 24.21,68.15 24.21,68.86 D55.A 24.59,68.89 24.59,68.15 24.71,68.02 24.86,68.02 25.22,68.38 25.22,69.8 24.97,70.05 24.2,70.05 23.95,70.3 23.95,70.95 24.2,71.2 25.1,71.2 25.48,71.58 25.48,73.12 24.57,74.03 24,74.03 23.83,73.86 23.83,72.97 24.46,72.34
  BOTTOM w0.102: v1(32.87,46.65) 32.64,46.88 32.64,47.9 32.46,48.08 32.46,51.02 36.53,55.09 36.53,56.71 37.03,57.22 37.03,64.59 35.43,66.19 29.67,66.19 28.93,66.93 28.22,66.93 27.13,68.02 23.25,68.02 v1(23,68.28)
LAN0_C-: length 54.6
  TOP w0.102: 23.19,74.88 23.78,74.29 24.67,74.29 25.73,73.23 25.73,71.47 25.2,70.94 24.31,70.94 24.21,70.84 24.21,70.41 24.31,70.31 25.07,70.31 25.48,69.9 25.48,68.28 24.97,67.77 24.71,67.77 24.59,67.64 24.59,66.65 D55.C 24.21,66.67 24.21,67.64 24.08,67.77 23.7,67.77 23.57,67.64 23.57,66.62 23.49,66.54 D83.3 v1(23,67.51) ; R424.2 33.38,45.64 33.38,45.72 33.17,45.92 32.66,45.92 32.41,46.17 32.41,46.43 v1(32.18,46.66)
  BOTTOM w0.102: v1(23,67.51) 23.25,67.77 27.02,67.77 28.11,66.67 28.83,66.67 29.56,65.94 35.33,65.94 36.78,64.49 36.78,57.33 36.27,56.82 36.27,55.19 32.21,51.13 32.21,47.98 32.38,47.8 32.38,46.86 v1(32.18,46.66)
LAN0_D+: length 54.9
  TOP w0.102: 20.65,74.88 20.29,74.52 20.29,73.54 20.78,73.05 20.78,71.45 21.03,71.2 21.92,71.2 22.17,70.95 22.17,70.3 21.92,70.05 19.38,70.05 19.18,69.85 19.18,68.15 19.31,68.02 19.38,68.02 19.51,68.15 19.51,68.89 D54.A 19.89,68.86 19.89,68.15 20.02,68.02 20.65,68.02 20.9,68.28 20.9,69.05 D83.6 21.29,69.06 21.29,68.57 21.61,68.25 v1(21.73,68.25) ; R215.2 30.97,45.71 30.97,45.85 31.7,46.58 31.7,47.35 v1(31.92,47.57)
  BOTTOM w0.102: v1(21.73,68.25) 21.99,68 22.25,68 22.5,67.74 22.5,67.12 22.82,66.8 26.95,66.8 27.56,66.19 28.6,66.19 29.34,65.46 35.03,65.46 36.27,64.21 36.27,57.53 35.79,57.04 35.79,55.45 31.7,51.36 31.7,47.78 v1(31.92,47.57)
LAN0_D-: length 54.8
  TOP w0.102: J22.9 19.38,72.52 20.07,73.21 20.26,73.21 20.52,72.95 20.52,71.34 20.93,70.94 21.82,70.94 21.92,70.84 21.92,70.41 21.82,70.31 19.27,70.31 18.92,69.96 18.92,68.05 19.2,67.77 19.38,67.77 19.51,67.64 19.51,66.65 D54.C 19.89,66.67 19.89,67.64 20.02,67.77 20.65,67.77 20.9,67.51 20.9,66.74 D83.1 21.29,66.73 21.29,67.17 21.61,67.49 v1(21.73,67.49) ; R214.2 30.72,45.77 30.72,45.96 31.45,46.69 31.45,47.35 v1(31.23,47.57)
  BOTTOM w0.102: v1(31.23,47.57) 31.45,47.78 31.45,51.46 35.53,55.55 35.53,57.15 36.02,57.63 36.02,64.11 34.92,65.2 29.23,65.2 28.5,65.94 27.45,65.94 26.84,66.55 22.71,66.55 22.25,67.01 22.25,67.64 22.15,67.74 21.99,67.74 v1(21.73,67.49)
LAN1_A+: length 72.2
  TOP w0.102: 47.07,74.88 47.57,74.88 48.08,74.37 48.08,73.84 47.85,73.61 46.24,73.61 45.92,73.92 45.92,75.28 46.54,75.9 47.6,75.9 49.73,73.76 49.73,68 49.63,67.89 49.48,67.89 49.41,67.97 49.41,68.91 D61.A 49.1,68.91 49.1,68.02 48.97,67.89 48.02,67.89 v1(47.76,68.15) D82.4 ; R266.2 63.79,45.7 63.79,46.7 62.28,48.21 62.28,49.25 61.55,49.99 61.07,49.99 60.81,50.24 60.81,50.35 v1(61,50.55)
  BOTTOM w0.102: v1(47.76,68.15) 48.02,67.89 48.21,67.89 48.34,68.02 48.34,69.06 47.82,69.57 43.79,69.57 42.37,68.15 42.37,66.65 41.86,66.14 41.86,58.37 42.57,57.66 51.63,57.66 52.12,58.14 57.81,58.14 59.89,56.06 59.89,53.92 60.78,53.04 60.78,50.77 v1(61,50.55)
LAN1_A-: length 72.3
  TOP w0.102: D82.3 v1(47.76,67.39) 48.02,67.64 48.97,67.64 49.1,67.51 49.1,66.62 D61.C 49.4,66.61 49.4,67.56 49.48,67.64 49.74,67.64 49.99,67.89 49.99,73.86 47.7,76.15 46.43,76.15 45.67,75.39 45.67,73.82 45.92,73.56 45.92,72.47 J23.3 ; v1(60.31,50.55) 60.55,50.3 60.55,50.14 60.96,49.73 61.44,49.73 62.03,49.15 62.03,48.11 63.54,46.6 63.54,45.7 R265.2
  BOTTOM w0.102: v1(47.76,67.39) 48.02,67.64 48.31,67.64 48.59,67.92 48.59,69.16 47.93,69.82 43.68,69.82 42.11,68.25 42.11,66.75 41.61,66.24 41.61,58.26 42.47,57.4 51.74,57.4 52.22,57.89 57.71,57.89 59.64,55.96 59.64,53.82 60.53,52.93 60.53,50.77 v1(60.31,50.55)
LAN1_B+: length 72.5
  TOP w0.102: D82.6 v1(45.86,68.15) 45.61,67.89 44.65,67.89 44.53,68.02 44.53,68.94 D60.A 44.27,68.94 44.27,68.02 44.15,67.89 44,67.89 43.89,68 43.89,69.82 44.12,70.05 48.95,70.05 49.23,70.33 49.23,70.92 48.95,71.2 47.3,71.2 47.19,71.3 47.19,72.88 v1(47.41,73.1) ; R264.2 61.04,45.73 61.04,48.2 60.67,48.58 60.67,48.73 v1(60.89,48.95)
  BOTTOM w0.102: v1(45.86,68.15) 46.12,67.89 46.25,67.89 46.38,68.02 46.38,68.6 46.15,68.83 44.2,68.83 43.26,67.89 43.26,66.39 42.6,65.73 42.6,58.75 42.96,58.39 51.3,58.39 51.79,58.88 58.24,58.88 60.66,56.46 60.66,54.28 61.85,53.09 61.85,50.04 61.42,49.61 61.04,49.61 60.67,49.23 60.67,49.16 v1(60.89,48.95) ; v1(47.41,73.1) 47.19,73.32 47.19,73.56 46.96,73.79 43.21,73.79 43,73.99 43,75.64 43.13,75.77 44.15,75.77 44.53,75.39 44.53,74.88
LAN1_B-: length 72.5
  TOP w0.102: v1(60.19,48.95) 60.41,48.73 60.41,48.47 60.79,48.1 60.79,45.74 R263.2 ; D82.1 v1(45.86,67.39) 45.61,67.64 44.65,67.64 44.53,67.51 44.53,66.59 D60.C 44.27,66.59 44.27,67.51 44.15,67.64 43.89,67.64 43.64,67.89 43.64,69.93 44.02,70.31 48.84,70.31 48.97,70.43 48.97,70.82 48.84,70.94 47.19,70.94 46.94,71.2 46.94,72.88 v1(46.72,73.1)
  BOTTOM w0.102: J23.7 41.91,73.53 46.86,73.53 46.94,73.45 46.94,73.32 v1(46.72,73.1) ; v1(60.19,48.95) 60.41,49.17 60.41,49.34 60.93,49.86 61.31,49.86 61.59,50.14 61.59,52.98 60.4,54.18 60.4,56.36 58.14,58.62 51.89,58.62 51.41,58.14 42.85,58.14 42.34,58.65 42.34,65.84 43,66.5 43,68 44.09,69.09 46.25,69.09 46.63,68.71 46.63,67.92 46.36,67.64 46.12,67.64 v1(45.86,67.39)
LAN1_C+: length 71.5
  TOP w0.102: J23.5 42.49,73.1 42.49,73.48 42.62,73.61 44.15,73.61 44.4,73.36 44.4,71.56 44.16,71.31 41.36,71.31 41.1,71.05 41.1,70.33 41.37,70.05 42.75,70.05 42.88,69.93 42.88,68 42.77,67.89 42.62,67.89 42.49,68.02 42.49,68.94 D59.A 42.24,68.94 42.24,68.02 42.11,67.89 41.16,67.89 v1(40.9,68.15) D81.4 ; R262.2 59.19,45.67 59.19,45.89 58.5,46.58 58.5,47.34 58.6,47.45 58.77,47.45 59.13,47.09 59.13,46.69 59.26,46.56 59.59,46.23 59.94,46.23 60.27,46.56 60.27,47.83 59.89,48.21 59.49,48.21 59.31,48.39 59.31,48.74 v1(59.51,48.95)
  BOTTOM w0.102: v1(40.9,68.15) 41.16,67.89 41.35,67.89 41.63,67.61 41.63,67.03 41.12,66.52 41.12,65.96 40.87,65.71 40.77,65.71 40.67,65.61 40.67,65.41 40.77,65.3 40.87,65.3 41.12,65.05 41.12,64.64 40.87,64.39 40.77,64.39 40.67,64.29 40.67,64.08 40.77,63.98 40.87,63.98 41.12,63.73 41.12,63.32 40.87,63.07 40.77,63.07 40.67,62.97 40.67,62.76 40.77,62.66 40.87,62.66 41.12,62.41 41.12,62 40.87,61.75 40.77,61.75 40.67,61.65 40.67,61.44 40.77,61.34 40.87,61.34 41.12,61.09 41.12,60.68 40.87,60.43 40.77,60.43 40.67,60.33 40.67,60.12 40.77,60.02 40.87,60.02 41.12,59.77 41.12,59.36 40.87,59.11 40.77,59.11 40.67,59 40.67,58.8 40.77,58.7 40.87,58.7 41.12,58.45 41.12,57.96 42.16,56.92 51.96,56.92 52.45,57.4 57.43,57.4 58.19,56.64 58.19,56.01 58.37,55.83 58.88,55.83 59.13,55.58 59.13,54.94 58.88,54.69 58.34,54.69 58.24,54.58 58.24,54.18 58.37,54.05 58.88,54.05 59.13,53.8 59.13,53.26 58.78,52.91 58.37,52.91 58.24,52.78 58.24,52.38 58.35,52.27 59,52.27 59.37,52.64 59.73,52.64 60.05,52.32 60.05,51.89 59.61,51.46 59.61,50.85 59.26,50.5 59.26,49.2 v1(59.51,48.95)
LAN1_C-: length 71.5
  TOP w0.102: D81.3 v1(40.9,67.39) 41.16,67.64 42.12,67.64 42.24,67.52 42.24,66.59 D59.C 42.49,66.59 42.49,67.51 42.62,67.64 42.88,67.64 43.13,67.89 43.13,70.03 42.85,70.31 41.48,70.31 41.35,70.43 41.35,70.94 41.47,71.06 44.26,71.06 44.65,71.45 44.65,73.46 44.25,73.86 42.63,73.86 41.99,74.5 41.99,74.88 ; R261.2 58.94,45.67 58.94,45.78 58.24,46.48 58.24,47.45 58.5,47.7 58.88,47.7 59.39,47.19 59.39,46.79 59.69,46.48 59.84,46.48 60.02,46.66 60.02,47.72 59.79,47.96 59.39,47.96 59.05,48.29 59.05,48.7 v1(58.81,48.95)
  BOTTOM w0.102: v1(40.9,67.39) 41.16,67.64 41.25,67.64 41.38,67.51 41.38,67.14 40.87,66.63 40.87,66.07 40.77,65.96 40.66,65.96 40.41,65.71 40.41,65.3 40.66,65.05 40.77,65.05 40.87,64.95 40.87,64.74 40.77,64.64 40.66,64.64 40.41,64.39 40.41,63.98 40.66,63.73 40.77,63.73 40.87,63.63 40.87,63.42 40.77,63.32 40.66,63.32 40.41,63.07 40.41,62.66 40.66,62.41 40.77,62.41 40.87,62.31 40.87,62.1 40.77,62 40.66,62 40.41,61.75 40.41,61.34 40.66,61.09 40.77,61.09 40.87,60.99 40.87,60.78 40.77,60.68 40.66,60.68 40.41,60.43 40.41,60.02 40.66,59.77 40.77,59.77 40.87,59.66 40.87,59.46 40.77,59.36 40.66,59.36 40.41,59.11 40.41,58.7 40.66,58.45 40.77,58.45 40.87,58.34 40.87,57.86 42.06,56.67 52.07,56.67 52.55,57.15 57.32,57.15 57.94,56.54 57.94,55.91 58.27,55.58 58.77,55.58 58.88,55.47 58.88,55.05 58.77,54.94 58.24,54.94 57.99,54.69 57.99,54.07 58.26,53.8 58.77,53.8 58.88,53.69 58.88,53.37 58.67,53.16 58.26,53.16 57.99,52.89 57.99,52.27 58.24,52.02 59.11,52.02 59.48,52.39 59.62,52.39 59.79,52.22 59.79,52 59.36,51.57 59.36,50.96 59,50.6 59,49.14 v1(58.81,48.95)
LAN1_D+: length 70.8
  TOP w0.102: 39.45,74.88 39.07,74.5 39.07,73.64 39.57,73.13 39.57,71.68 40.34,70.92 40.34,70.33 39.93,69.93 39.45,69.93 38.43,70.94 37.27,70.94 37.03,70.71 37.03,68 37.13,67.89 37.28,67.89 37.36,67.97 37.36,68.89 D58.A 37.66,68.94 37.66,68.02 37.79,67.89 38.75,67.89 v1(39,68.15) D81.6 ; R260.2 56.62,45.66 56.62,46.03 56.34,46.3 55.93,46.3 55.83,46.41 55.83,46.71 55.93,46.81 56.85,46.81 57.1,47.06 57.1,47.7 56.85,47.96 55.93,47.96 55.83,48.06 55.83,48.46 55.96,48.59 56.29,48.59 56.74,49.05 56.97,49.05 56.99,49.03 v1(57.06,49.03)
  BOTTOM w0.102: v1(57.06,49.03) 57.16,49.03 57.3,49.18 57.3,49.45 57.67,49.82 57.67,50.18 56.46,51.38 52.6,51.38 52.5,51.49 52.5,51.79 52.6,51.89 56.51,51.89 57.05,52.43 57.05,52.78 56.8,53.04 56.57,53.04 56.46,53.14 56.46,53.56 56.57,53.67 57.18,53.67 57.43,53.92 57.43,55.88 56.65,56.67 52.65,56.67 52.17,56.18 41.76,56.18 39.98,57.96 39.98,67.41 39.5,67.89 39.25,67.9 v1(39,68.15)
LAN1_D-: length 70.8
  TOP w0.102: D81.1 39,67.38 v1(39,67.39) 38.74,67.64 37.78,67.64 37.66,67.52 37.66,66.59 D58.C 37.36,66.65 37.36,67.56 37.28,67.64 37.03,67.64 36.78,67.89 36.78,70.82 37.16,71.2 38.54,71.2 39.55,70.18 39.83,70.18 40.08,70.43 40.08,70.82 39.32,71.58 39.32,73.02 38.91,73.43 38.86,73.48 38.56,73.48 38.18,73.1 J23.9 ; R259.2 56.36,45.66 56.36,45.92 56.24,46.05 55.83,46.05 55.58,46.3 55.58,46.81 55.83,47.07 56.74,47.07 56.85,47.17 56.85,47.6 56.74,47.7 55.83,47.7 55.58,47.96 55.58,48.57 55.85,48.84 56.18,48.84 56.54,49.21 56.54,49.5 v1(56.57,49.52)
  BOTTOM w0.102: v1(39,67.39) 39.26,67.64 39.39,67.64 39.73,67.31 39.73,57.86 41.65,55.93 52.27,55.93 52.76,56.41 56.54,56.41 57.18,55.78 57.18,54.03 57.07,53.92 56.46,53.92 56.21,53.67 56.21,53.04 56.46,52.78 56.7,52.78 56.8,52.68 56.8,52.54 56.41,52.15 52.5,52.15 52.25,51.9 52.25,51.38 52.5,51.13 56.36,51.13 57.42,50.07 57.42,49.93 57.05,49.56 56.6,49.56 v1(56.57,49.52)
LVDS_EN_GPIO3_A2: length 93.8
  TOP w0.127: v1(69.75,60.15) 69.75,60.25 70.17,60.67 J2.65 ; v1(37.85,10.44) 37.8,10.49 35.64,10.49 34.04,12.08 R137.2
  BOTTOM w0.127: v1(37.85,10.44) 37.85,12.55 37.97,12.67 37.97,18.41 39.9,20.34 42.08,20.34 42.32,20.11 42.32,18.67 42.52,18.46 42.52,18.46 42.85,18.14 45.27,18.14 46.58,19.45 46.58,19.91 47.47,20.8 49.5,20.8 51,22.3 51,26.87 49.99,27.89 49.99,37.03 49.35,37.67 49.35,40.84 51.21,42.7 51.21,43.97 52.32,45.08 52.32,45.84 52.69,46.21 53.05,46.21 55.12,44.14 65.2,44.14 65.21,44.15 65.23,44.15 67.89,46.81 67.89,60.53 68.15,60.78 69.16,60.78 69.75,60.2 v1(69.75,60.15)
LVDS_ON_: length 37.5
  TOP w0.127: v1(33.48,11.53) 33.17,11.53 32.56,10.92 32.56,10.62 31.85,9.91 31.85,8.56 31.24,7.95 31.24,2.44 v1(31.62,2.06) ; Q7.2 33.6,17.09 33.72,17.22 34.09,17.22 v1(34.16,17.14) 34.24,17.22 34.81,17.22 R135.2 35.51,17.03 35.51,16.91 R133.2
  BOTTOM w0.127: v1(31.62,2.06) 31.62,2.01 31.5,1.88 15.91,1.88 J18.4 ; v1(33.48,11.53) 33.17,11.84 33.17,13.87 33.86,14.55 33.86,15.9 34.16,16.21 v1(34.16,17.14)
LVDS_ON_GPIO3_A1: length 124
  TOP w0.127: v1(88.06,52.53) 87.71,52.53 84.28,49.1 84.28,42.88 85.04,42.11 85.04,37.92 85.78,37.19 v1(85.78,36.8) ; J2.67 69.67,62.23 69.19,62.71 v1(69.19,62.74) ; 35.96,18.44 35.68,18.16 34.21,18.16 33.87,18.5 Q7.3 33.1,18.95 33.4,19.25 34.57,19.25 35.37,20.05 36.49,20.05 38.07,21.64 39.62,21.64 40.06,21.21 43.43,21.21 43.76,21.54 47.07,21.54 48.72,23.19 48.72,24.8 50.4,26.49 v1(51.51,26.49) ; 35.96,18.44 R135.1 ; 35.96,18.44 R132.2
  BOTTOM w0.127: v1(85.78,36.8) 84.91,37.67 78.82,37.67 68.02,26.87 51.89,26.87 v1(51.51,26.49) ; v1(88.06,52.53) 87.97,52.62 87.97,52.79 88.95,53.77 88.95,55.42 92.61,59.08 92.61,61.14 91.8,61.95 83.69,61.95 82.94,62.7 82.94,63.59 82.04,64.49 80.34,64.49 79.58,65.25 71.35,65.25 69.8,63.7 69.42,63.7 69.19,63.47 v1(69.19,62.74)
LVDS_PWM13: length 35.1
  TOP w0.127: v1(32.33,1.83) 32.33,2.21 31.57,2.97 31.57,7.82 32.16,8.41 32.16,9.78 v1(33.12,10.74) ; U14.4 31.32,13.14 v1(31.7,13.52) 32.13,13.52 R138.2
  BOTTOM w0.127: v1(32.33,1.83) 32.08,1.57 14.21,1.57 J18.3 ; v1(31.7,13.52) 32.92,12.3 32.92,10.95 v1(33.12,10.74)
LVDS_TX0_CLKN: length 19
  TOP w0.102: v1(10.94,40.63) 10.62,40.95 10.62,41.94 9.68,42.88 9.22,42.88 8.97,42.62 8.97,41.08 8.86,40.97 8.56,40.97 8.46,41.08 8.46,42.35 8.18,42.62 6.25,42.62 6.05,42.83 6.05,43.29 6.24,43.48 J16.15
  BOTTOM w0.102: R127.2 16.19,38.35 11.58,38.35 10.62,39.32 10.62,40.31 v1(10.94,40.63)
LVDS_TX0_CLKP: length 19.1
  TOP w0.102: v1(10.04,40.63) 10.36,40.95 10.36,41.83 9.58,42.62 9.32,42.62 9.22,42.52 9.22,40.97 8.97,40.72 8.46,40.72 8.2,40.97 8.2,42.24 8.08,42.37 6.15,42.37 5.79,42.72 5.79,43.15 5.47,43.48 J16.16
  BOTTOM w0.102: R126.2 16.21,38.1 11.48,38.1 10.36,39.21 10.36,40.31 v1(10.04,40.63)
LVDS_TX0_D0N: length 20
  TOP w0.102: v1(13.59,42.24) 13.18,41.84 13.1,41.84 12.85,41.58 12.85,37.21 13.28,36.78 13.28,35.23 12.7,34.65 6.35,34.65 6.06,34.93 6.06,35.38 6.16,35.48 J16.7
  BOTTOM w0.102: R122.8 16.4,41.31 16.25,41.16 14.89,41.16 14.15,41.91 13.89,41.91 13.59,42.21 v1(13.59,42.24)
LVDS_TX0_D0P: length 20
  TOP w0.102: v1(13.59,41.34) 13.35,41.58 13.21,41.58 13.11,41.48 13.11,37.32 13.54,36.88 13.54,35.13 12.8,34.39 6.24,34.39 5.81,34.83 5.81,35.19 5.52,35.48 J16.8
  BOTTOM w0.102: v1(13.59,41.34) 13.91,41.67 14.03,41.67 14.79,40.91 16.24,40.91 16.39,40.76 R122.7
LVDS_TX0_D1N: length 19.9
  TOP w0.102: v1(11.63,40.38) 11.41,40.16 11.12,40.16 10.87,39.91 10.87,37.01 10.54,36.68 10.11,36.68 9.86,36.42 9.86,35.76 9.73,35.64 9.32,35.64 9.22,35.74 9.22,37.29 8.97,37.54 8.33,37.54 8.08,37.29 8.08,36.91 7.77,36.6 6.15,36.6 6.02,36.73 6.02,37.34 6.16,37.48 J16.9
  BOTTOM w0.102: v1(11.63,40.38) 11.87,40.14 12.63,40.14 12.9,39.87 12.9,39.42 13.01,39.32 13.82,39.32 13.92,39.42 13.92,39.77 14.31,40.16 16.26,40.16 16.36,40.26 R122.6
LVDS_TX0_D1P: length 19.8
  TOP w0.102: v1(11.63,39.68) 11.41,39.9 11.23,39.9 11.13,39.8 11.13,36.91 10.64,36.42 10.21,36.42 10.11,36.32 10.11,35.66 9.83,35.38 9.22,35.38 8.97,35.63 8.97,37.18 8.86,37.29 8.44,37.29 8.33,37.18 8.33,36.8 7.88,36.35 6.04,36.35 5.77,36.62 5.77,37.16 5.45,37.48 J16.10
  BOTTOM w0.102: R122.5 16.42,39.71 16.28,39.85 14.36,39.85 14.17,39.66 14.17,39.32 13.92,39.07 12.9,39.07 12.65,39.32 12.65,39.76 12.52,39.89 11.84,39.89 v1(11.63,39.68)
LVDS_TX0_D2N: length 19.6
  TOP w0.102: J16.11 6.14,39.48 6.04,39.38 6.04,38.88 6.25,38.66 7.95,38.66 8.2,38.92 8.2,39.96 8.45,40.21 9.09,40.21 9.35,39.95 9.35,38.41 9.45,38.3 9.99,38.3 v1(10.21,38.52)
  BOTTOM w0.102: v1(10.21,38.52) 10.5,38.24 10.63,38.24 10.92,37.95 10.92,36.7 11.04,36.59 11.4,36.59 11.51,36.69 11.51,37.27 11.78,37.54 12.27,37.54 12.57,37.24 12.57,36.71 12.69,36.59 12.99,36.59 13.16,36.76 13.16,37.29 13.41,37.54 13.92,37.54 14.17,37.29 14.17,36.72 14.29,36.6 16.13,36.6 16.29,36.77 R123.8
LVDS_TX0_D2P: length 19.6
  TOP w0.102: v1(10.24,37.8) 9.98,38.05 9.35,38.05 9.09,38.3 9.09,39.85 8.99,39.95 8.56,39.95 8.46,39.85 8.46,38.81 8.05,38.4 6.15,38.4 5.78,38.77 5.78,39.28 5.58,39.48 J16.12
  BOTTOM w0.102: R123.7 16.31,36.22 16.18,36.35 14.18,36.35 13.92,36.61 13.92,37.18 13.81,37.29 13.51,37.29 13.41,37.19 13.41,36.65 13.09,36.33 12.59,36.33 12.32,36.6 12.32,37.13 12.17,37.29 11.89,37.29 11.76,37.16 11.76,36.59 11.51,36.33 10.93,36.33 10.67,36.6 10.67,37.84 10.53,37.98 10.42,37.98 v1(10.24,37.8)
LVDS_TX0_D3N: length 20.9
  TOP w0.102: v1(12.09,35.76) 11.89,35.97 11.89,36.4 12.37,36.88 12.37,41.25 9.02,44.6 6.25,44.6 6.04,44.81 6.04,45.31 6.21,45.48 J16.17
  BOTTOM w0.102: v1(12.09,35.76) 12.09,35.74 11.89,35.53 11.89,35.17 12.24,34.81 14.31,34.81 15.09,35.59 16.15,35.59 16.29,35.72 R123.6
LVDS_TX0_D3P: length 21
  TOP w0.102: v1(11.39,35.75) 11.63,36 11.63,36.5 12.12,36.99 12.12,41.14 8.91,44.35 6.15,44.35 5.79,44.71 5.79,45.14 5.45,45.48 J16.18
  BOTTOM w0.102: v1(11.39,35.75) 11.63,35.51 11.63,35.06 12.14,34.56 14.42,34.56 15.19,35.33 16.15,35.33 16.32,35.17 R123.5
MIC1_INN: length 203.8
  TOP w0.203: v1(126.44,63.2) 126.44,63.5 126.24,63.7 D97.2 125.78,62.56 C66.2 ; v1(34.82,26.52) 34.14,27.2 28.04,27.2 25.68,29.57 25.68,30.3 25.53,30.45 24.79,30.45 23.04,32.21 18.87,32.21 16.48,34.59 16.48,36.73 15.29,37.92 15.29,50 16.33,51.04 16.73,51.44 18.37,51.44 20.57,51.44 21.25,52.11 21.63,52.11 21.92,52.4 J2.250
  BOTTOM w0.203: v1(126.44,63.2) 126.67,62.97 127.56,62.97 128.04,62.48 128.04,61.85 129.49,60.4 129.49,48.72 128.47,47.7 128.47,40.08 126.44,38.05 115.47,38.05 113.44,36.02 112.6,36.02 110.13,33.55 101.75,33.55 101,32.8 97.4,32.8 95.35,30.76 89.87,30.76 89.05,29.95 88.24,29.95 87.83,29.54 87.83,28.65 86.39,27.2 86.39,26.31 77.17,17.09 77.17,12.9 70.31,6.05 38.45,6.05 35.28,9.22 35.28,13.61 35.59,13.92 35.59,25.76 v1(34.82,26.52)
MIC1_INP: length 202.3
  TOP w0.203: C64.2 125.41,61.98 126.11,61.98 126.47,62.33 v1(126.47,62.43) ; J2.248 22.42,52.4 21.77,51.74 21.37,51.74 20.73,51.1 18.24,51.1 16.87,51.1 16.47,50.71 15.62,49.86 15.62,38.1 16.85,36.87 16.85,34.73 19.05,32.54 23.19,32.54 24.94,30.79 25.85,30.79 26.06,30.58 26.06,29.67 28.19,27.53 34.59,27.53 v1(34.87,27.25)
  BOTTOM w0.203: v1(34.87,27.25) 35.36,26.77 35.36,26.47 35.94,25.88 35.94,13.72 35.61,13.39 35.61,9.43 38.61,6.43 70.18,6.43 76.78,13.03 76.78,17.22 86.06,26.49 86.06,27.38 87.45,28.78 87.45,29.67 88.06,30.28 88.92,30.28 89.73,31.09 95.17,31.09 97.24,33.16 100.85,33.16 101.6,33.91 109.98,33.91 112.47,36.4 113.33,36.4 115.37,38.43 126.31,38.43 128.09,40.21 128.09,47.83 129.11,48.84 129.11,60.27 127.71,61.67 127.71,62.33 127.41,62.64 126.67,62.64 v1(126.47,62.43)
MIPI_CSI_CLK0N: length 6
  TOP w0.102: R148.2 58.32,14.02 58,13.71 58,13.31 58.1,13.21 58.1,12.96 58.23,12.84 D99.1 D99.10 58.23,11.11 58.12,11 58.12,10.13 57.9,9.92 57.9,9.69 58.02,9.57 J19.17
